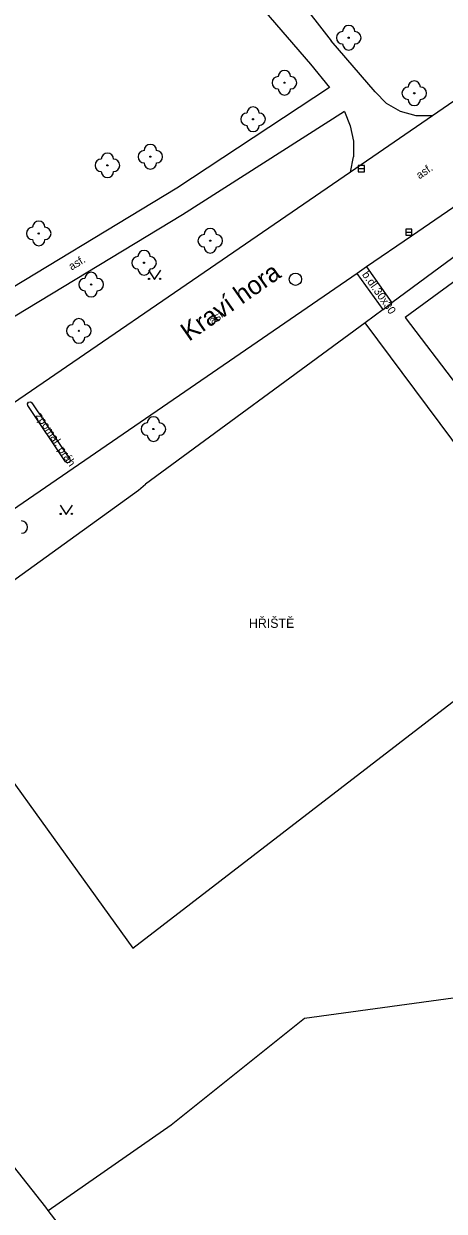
# Model space of a CAD drawing. Extents: x -600391 to -599491, y -1160176 to -1159402.
# Drawn here: x -599727.5 to -599693.4, y -1159796.2 to -1159699.8 of the extents above; entities that cross this region are included whole.
import ezdxf

# ---------------------------------------------------------------- set-up
doc = ezdxf.new("R2010")
doc.units = 0
for name, color, linetype in [('Level 10', 7, 'Continuous'), ('Level 11', 7, 'Continuous'), ('Level 22', 7, 'Continuous'), ('Level 27', 7, 'Continuous'), ('Level 36', 7, 'Continuous'), ('Level 40', 7, 'Continuous'), ('Level 41', 7, 'Continuous'), ('Level 42', 7, 'Continuous'), ('Level 50', 7, 'Continuous'), ('Level 51', 7, 'Continuous'), ('Level 7', 7, 'Continuous'), ('Level 8', 7, 'Continuous')]:
    doc.layers.add(name, color=color, linetype=linetype)

msp = doc.modelspace()

# ---------------------------------------------------------------- linework, layer by layer
at = {"layer": 'Level 10'}
for points in [[(-599681.97, -1159698.73), (-599694.34, -1159707.24)], [(-599679.71, -1159705.81), (-599696.04, -1159717), (-599699.69, -1159719.51), (-599700.44, -1159720.03)], [(-599694.34, -1159707.24), (-599700.97, -1159711.82)], [(-599700.97, -1159711.82), (-599713.8, -1159720.62)], [(-599700.44, -1159720.03), (-599750.59, -1159754.5), (-599752.54, -1159756.01)], [(-599713.8, -1159720.62), (-599723.5, -1159727.27)], [(-599723.5, -1159727.27), (-599733.67, -1159734.23)]]:
    msp.add_lwpolyline(points, dxfattribs=at)
at = {"layer": 'Level 11'}
for points in [[(-599711.21, -1159689.99), (-599702.54, -1159701.14)], [(-599708, -1159698.66), (-599704.24, -1159703.04), (-599702.69, -1159704.95)], [(-599698.98, -1159705.3), (-599702.54, -1159701.14)], [(-599702.69, -1159704.95), (-599715.07, -1159713.12), (-599731.34, -1159722.96), (-599740.14, -1159728.45)], [(-599696.92, -1159706.89), (-599698.06, -1159706.23), (-599698.98, -1159705.3)], [(-599701.48, -1159706.88), (-599714.62, -1159715.28), (-599730.12, -1159724.66)], [(-599701.48, -1159706.88), (-599701, -1159708.06), (-599700.75, -1159709.3), (-599700.74, -1159710.57)], [(-599695.65, -1159707.24), (-599696.92, -1159706.89)], [(-599694.34, -1159707.24), (-599695.65, -1159707.24)], [(-599700.97, -1159711.82), (-599700.74, -1159710.57)], [(-599682.29, -1159713.18), (-599696.56, -1159723.62), (-599683.81, -1159740.34), (-599676.15, -1159733.85)], [(-599699.69, -1159719.51), (-599697.63, -1159722.42)], [(-599698.33, -1159722.96), (-599700.44, -1159720.03)], [(-599736.1, -1159750.56), (-599718.63, -1159774.82), (-599682.64, -1159747.09), (-599699.8, -1159724.04)], [(-599727.15, -1159730.77), (-599727.18, -1159730.62), (-599727.09, -1159730.48), (-599726.93, -1159730.45), (-599726.8, -1159730.54)], [(-599724.11, -1159735.33), (-599727.15, -1159730.77)], [(-599723.75, -1159735.09), (-599726.8, -1159730.54)], [(-599723.75, -1159735.09), (-599723.72, -1159735.25), (-599723.81, -1159735.38), (-599723.97, -1159735.41), (-599724.11, -1159735.33)], [(-599725.5, -1159796.11), (-599715.54, -1159789.16), (-599704.71, -1159780.49), (-599690.68, -1159778.59), (-599681.74, -1159775.04), (-599678.56, -1159775.99), (-599673.64, -1159770.59), (-599678.72, -1159765.67), (-599671.9, -1159759.48), (-599675.32, -1159754.67)]]:
    msp.add_lwpolyline(points, dxfattribs=at)
at = {"layer": 'Level 22'}
for centre in [(-599701.13, -1159700.9), (-599706.34, -1159704.55), (-599695.81, -1159705.41), (-599708.89, -1159707.52), (-599717.22, -1159710.56), (-599720.7, -1159711.26), (-599726.27, -1159716.79), (-599712.36, -1159717.38), (-599717.73, -1159719.17), (-599722.02, -1159720.94), (-599723.02, -1159724.7), (-599716.97, -1159732.67)]:
    msp.add_circle(centre, 0.05, dxfattribs=at)
for centre, start, end in [((-599701.63, -1159700.9), 90, 270), ((-599701.13, -1159700.4), 0, 180), ((-599700.63, -1159700.9), 270, 90), ((-599701.13, -1159701.4), 180, 0), ((-599706.84, -1159704.55), 90, 270), ((-599706.34, -1159704.05), 0, 180), ((-599705.84, -1159704.55), 270, 90), ((-599706.34, -1159705.05), 180, 0), ((-599696.31, -1159705.41), 90, 270), ((-599695.81, -1159704.91), 0, 180), ((-599695.31, -1159705.41), 270, 90), ((-599695.81, -1159705.91), 180, 0), ((-599709.39, -1159707.52), 90, 270), ((-599708.89, -1159707.02), 0, 180), ((-599708.39, -1159707.52), 270, 90), ((-599708.89, -1159708.02), 180, 0), ((-599717.72, -1159710.56), 90, 270), ((-599717.22, -1159710.06), 0, 180), ((-599716.72, -1159710.56), 270, 90), ((-599721.2, -1159711.26), 90, 270), ((-599720.7, -1159710.76), 0, 180), ((-599720.2, -1159711.26), 270, 90), ((-599717.22, -1159711.06), 180, 0), ((-599720.7, -1159711.76), 180, 0), ((-599726.27, -1159716.29), 0, 180), ((-599726.77, -1159716.79), 90, 270), ((-599725.77, -1159716.79), 270, 90), ((-599712.36, -1159716.88), 0, 180), ((-599726.27, -1159717.29), 180, 0), ((-599712.86, -1159717.38), 90, 270), ((-599711.86, -1159717.38), 270, 90), ((-599718.23, -1159719.17), 90, 270), ((-599717.73, -1159718.67), 0, 180), ((-599717.23, -1159719.17), 270, 90), ((-599712.36, -1159717.88), 180, 0), ((-599717.73, -1159719.67), 180, 0), ((-599722.52, -1159720.94), 90, 270), ((-599722.02, -1159720.44), 0, 180), ((-599721.52, -1159720.94), 270, 90), ((-599722.02, -1159721.44), 180, 0), ((-599723.52, -1159724.7), 90, 270), ((-599723.02, -1159724.2), 0, 180), ((-599722.52, -1159724.7), 270, 90), ((-599723.02, -1159725.2), 180, 0), ((-599717.47, -1159732.67), 90, 270), ((-599716.97, -1159732.17), 0, 180), ((-599716.47, -1159732.67), 270, 90), ((-599716.97, -1159733.17), 180, 0), ((-599727.68, -1159740.63), 270, 90)]:
    msp.add_arc(centre, 0.5, start, end, dxfattribs=at)
at = {"layer": 'Level 27'}
for p, q in [((-599700.36, -1159711.53), (-599699.86, -1159711.53)), ((-599696.5, -1159716.68), (-599696, -1159716.68))]:
    msp.add_line(p, q, dxfattribs=at)
for points in [[(-599700.36, -1159711.78), (-599699.86, -1159711.78), (-599699.86, -1159711.28), (-599700.36, -1159711.28)], [(-599696.5, -1159716.93), (-599696, -1159716.93), (-599696, -1159716.43), (-599696.5, -1159716.43)]]:
    msp.add_lwpolyline(points, close=True, dxfattribs=at)
msp.add_circle((-599705.45, -1159720.51), 0.5, dxfattribs=at)
at = {"layer": 'Level 36'}
for points in [[(-599717.37, -1159719.78), (-599716.87, -1159720.53), (-599716.37, -1159719.78)], [(-599724.54, -1159738.86), (-599724.04, -1159739.61), (-599723.54, -1159738.86)]]:
    msp.add_lwpolyline(points, dxfattribs=at)
for centre in [(-599717.32, -1159720.48), (-599716.421, -1159720.48), (-599724.49, -1159739.56), (-599723.591, -1159739.56)]:
    msp.add_circle(centre, 0.05, dxfattribs=at)
at = {"layer": 'Level 51'}
msp.add_lwpolyline([(-599722.17, -1159800.44), (-599725.5, -1159796.11), (-599725.71, -1159795.83)], dxfattribs=at)
at = {"layer": 'Level 7'}
for points in [[(-599676.22, -1159707.08), (-599683.17, -1159711.79), (-599693.2, -1159719.15), (-599697.63, -1159722.42)], [(-599698.33, -1159722.96), (-599699.8, -1159724.04), (-599717.6, -1159737.15)], [(-599736.1, -1159750.56), (-599718.19, -1159737.64)], [(-599725.71, -1159795.83), (-599746.89, -1159768.96)]]:
    msp.add_lwpolyline(points, dxfattribs=at)
at = {"layer": 'Level 8'}
for points in [[(-599698.33, -1159722.96), (-599697.63, -1159722.42)], [(-599718.19, -1159737.64), (-599717.6, -1159737.15)]]:
    msp.add_lwpolyline(points, dxfattribs=at)

# ---------------------------------------------------------------- texts
at = {"layer": 'Level 40'}
for s, rotation, p in [('asf.', 34.53815, (-599695.39, -1159712.41)), ('asf.', 31.26129, (-599723.61, -1159719.81)), ('b.dl.30x30', 305, (-599700.08, -1159720.13)), ('asf.', 36.4574, (-599712.17, -1159724.22))]:
    msp.add_text(s, height=0.65, rotation=rotation, dxfattribs=at).set_placement(p)
at = {"layer": 'Level 41'}
msp.add_text('HŘIŠTĚ', height=0.75, dxfattribs=at).set_placement((-599709.22, -1159748.81))
at = {"layer": 'Level 42'}
msp.add_text('zpomal. práh', height=0.65, rotation=303.81187, dxfattribs=at).set_placement((-599726.56, -1159731.6))
at = {"layer": 'Level 50'}
msp.add_text('Kraví hora', height=1.5, rotation=35.0354, dxfattribs=at).set_placement((-599714.085, -1159725.593))

doc.saveas('drawing.dxf')
